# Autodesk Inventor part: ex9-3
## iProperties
Created: 2006-03
Part Number: ex9-3
Document SubType Name: Sheet Metal
Designer: Elise Moss
Author: Elise Moss
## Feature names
1. Plate1
2. Bend1
3. Plate2
4. Bend2
5. Cut1
